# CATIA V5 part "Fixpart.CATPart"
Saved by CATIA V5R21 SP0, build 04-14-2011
Part number: Fixpart
Bounding box of the stored display mesh (mm): x 114.05 to 153.05, y 317.865 to 356.76, z -739.218 to -725.236
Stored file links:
  C:\Users\Home\Desktop\Rollkurve_4\Fixpart.CATPart

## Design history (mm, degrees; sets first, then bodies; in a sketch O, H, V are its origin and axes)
AxisSystem1: origin (144.05, 324.7603, -732.2273), X (1, 0, 0), Y (0, 1, 0), Z (0, 0, 1)
Body1 (main body)
  Point1: type Center, Curve edge [face of Solid1 | face of Solid1]
  Point2: (5.25, 32, 0), relative to Point1, in AxisSystem1
Body2 "WELLE"
  Solid1 "Volumen.1": solid without history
